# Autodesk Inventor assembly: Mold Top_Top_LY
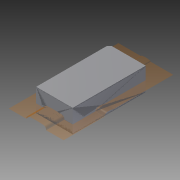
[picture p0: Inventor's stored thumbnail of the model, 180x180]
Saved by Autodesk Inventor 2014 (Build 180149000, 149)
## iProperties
Created: 2009-12
Part Number: Mold Top_Top_LY
Document SubType Name: Assembly
Designer: gaom
Author: gaom
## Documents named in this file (2)
- C:\Users\iTools\Desktop\tutorial files\Mold\Mold Structural Assembly\Mold Top\Mold Top_Top_LY.iam
- C:\Users\iTools\Desktop\tutorial files\Mold\Mold Structural Assembly\Mold Top\Mold Top_Top_PZ.iam
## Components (1 placed, 1 different names)
1. Mold Top_Top_PZ:1 [sub-assembly] — Flush:1, Flush:2, Flush:3
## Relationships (3: Flush 3)
- Flush:1: Mold Top_Top_PZ:1
- Flush:2: Mold Top_Top_PZ:1
- Flush:3: Mold Top_Top_PZ:1
